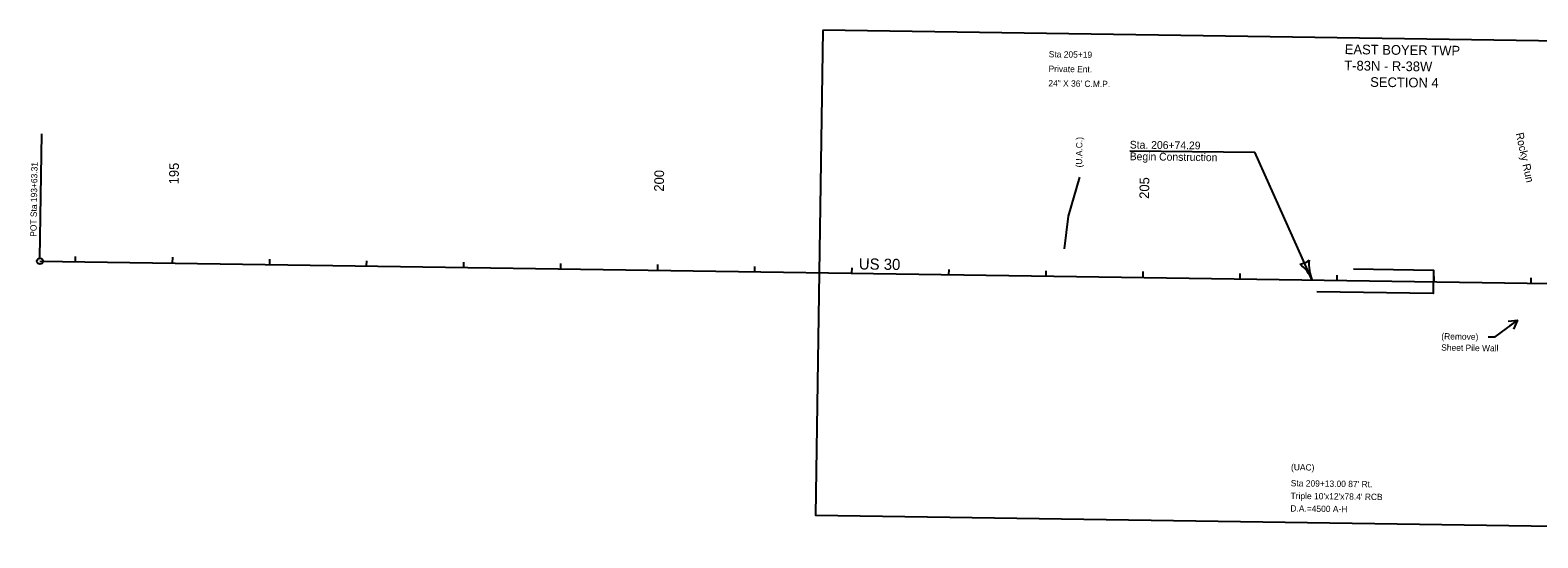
# Model space of a CAD drawing. Extents: x 14295116 to 14303545, y 8637313 to 8653417.
# Drawn here: x 14299276 to 14300829, y 8652720 to 8653243 of the extents above; entities that cross this region are included whole.
import ezdxf

# ---------------------------------------------------------------- set-up
doc = ezdxf.new("R2010")
doc.units = 0
for name, color, linetype in [('dsnCellElements', 7, 'Continuous'), ('dsnCellsNorthArrow', 7, 'Continuous'), ('dsnNonPlotable', 7, 'Continuous'), ('dsnProfileBarGraphArrows', 7, 'Continuous'), ('dsnProfileGradePropCircle', 7, 'Continuous'), ('dsnShtPortLev01', 7, 'Continuous'), ('dsnTextCulvertProp', 7, 'Continuous'), ('dsnTextEntranceProp', 7, 'Continuous'), ('dsnTextNote', 7, 'Continuous'), ('dsnTextProfileBarGraphLeft', 7, 'Continuous'), ('dsnTextProfileBarGraphRight', 7, 'Continuous'), ('dsnTextProfileGradeProp', 7, 'Continuous'), ('dsnTextRoadwayLabel', 7, 'Continuous'), ('PhoNotesDesign', 7, 'Continuous')]:
    doc.layers.add(name, color=color, linetype=linetype)

msp = doc.modelspace()

# ---------------------------------------------------------------- linework, layer by layer
at = {"layer": 'dsnCellElements'}
msp.add_lwpolyline([(14300092.5, 8653243.2), (14300085, 8652743.2), (14301652.4, 8652720), (14301659.8, 8653219.9)], close=True, dxfattribs=at)
at = {"layer": 'dsnCellsNorthArrow'}
for p in [(14300408.9, 8653118.9), (14300596.8, 8652985.7)]:
    msp.add_line(p, (14300537.8, 8653117.3), dxfattribs=at)
for centre, radius, start, end in [((14300582.8, 8653018.5), 16.4, 275.2724, 310.7391), ((14300557.6, 8652969.1), 42.5, 23.0058, 51.0783), ((14300635.9, 8653002.3), 42.5, 174.9333, 203.0058)]:
    msp.add_arc(centre, radius, start, end, dxfattribs=at)
at = {"layer": 'dsnProfileBarGraphArrows'}
for p in [(14300798.7, 8652943.3), (14300800.6, 8652938.4), (14300804.6, 8652935.2)]:
    msp.add_line(p, (14300808.6, 8652944.4), dxfattribs=at)
msp.add_lwpolyline([(14300778, 8652927), (14300785.4, 8652927.2), (14300808.6, 8652944.4)], dxfattribs=at)
at = {"layer": 'dsnProfileGradePropCircle'}
msp.add_line((14299285.9, 8653008.3), (14299287.8, 8653136.2), dxfattribs=at)
msp.add_circle((14299285.9, 8653005.1), 3.13, dxfattribs=at)
at = {"layer": 'dsnShtPortLev01'}
msp.add_line((14299285.9, 8653005.1), (14302066.2, 8652963.9), dxfattribs=at)
at = {"layer": 'dsnTextCulvertProp'}
msp.add_lwpolyline([(14300639.5, 8652997.1), (14300721.7, 8652995.8), (14300721.3, 8652971.8), (14300601.6, 8652973.6)], dxfattribs=at)
at = {"layer": 'dsnTextEntranceProp'}
msp.add_lwpolyline([(14300341.5, 8653017.9), (14300345.8, 8653051.5), (14300357.4, 8653091.8)], dxfattribs=at)
at = {"layer": 'dsnTextProfileGradeProp'}
for p, q in [((14299322.6, 8653004.6), (14299322.6, 8653010.1)), ((14299422.6, 8653003.1), (14299422.7, 8653009.2)), ((14299522.6, 8653001.6), (14299522.6, 8653007.1)), ((14299622.5, 8653000.2), (14299622.6, 8653005.6)), ((14299722.5, 8652998.7), (14299722.6, 8653004.2)), ((14299822.5, 8652997.2), (14299822.6, 8653002.7)), ((14299922.5, 8652995.7), (14299922.6, 8653001.8)), ((14300022.5, 8652994.2), (14300022.6, 8652999.7)), ((14300122.5, 8652992.7), (14300122.6, 8652998.2)), ((14300222.5, 8652991.2), (14300222.6, 8652996.7)), ((14300322.5, 8652989.8), (14300322.6, 8652995.3)), ((14300422.5, 8652988.3), (14300422.6, 8652994.4)), ((14300522.5, 8652986.8), (14300522.6, 8652992.3)), ((14300622.5, 8652985.3), (14300622.5, 8652990.8)), ((14300722.5, 8652983.8), (14300722.5, 8652989.3)), ((14300822.4, 8652982.3), (14300822.5, 8652987.8))]:
    msp.add_line(p, q, dxfattribs=at)
at = {"layer": 'PhoNotesDesign'}
msp.add_line((14299285.9, 8653005.1), (14303544.9, 8652941.9), dxfattribs=at)

# ---------------------------------------------------------------- texts
at = {"layer": 'dsnCellsNorthArrow'}
for s, p in [('Sta. 206+74.29', (14300408.8, 8653121.2)), ('Begin Construction', (14300408.7, 8653109.2))]:
    msp.add_text(s, height=8, rotation=359.2807, dxfattribs=at).set_placement(p)
at = {"layer": 'dsnNonPlotable'}
for s, p in [('195', (14299428.8, 8653084.2)), ('200', (14299928.7, 8653076.7)), ('205', (14300428.7, 8653069.3))]:
    msp.add_text(s, height=10, rotation=89.1493, dxfattribs=at).set_placement(p)
at = {"layer": 'dsnProfileBarGraphArrows'}
for s, height, rotation, p in [('(U.A.C.)', 6.5, 89.2807, (14300359.7, 8653101.7)), ('US 30', 11.5, 359.1493, (14300129.6, 8652996.6)), ('(Remove)', 6.5, 359.2287, (14300729.8, 8652924.5)), ('Sheet Pile Wall', 6.5, 359.2287, (14300729.7, 8652912.9))]:
    msp.add_text(s, height=height, rotation=rotation, dxfattribs=at).set_placement(p)
at = {"layer": 'dsnProfileGradePropCircle'}
msp.add_text('POT Sta 193+63.31', height=6.5, rotation=89.1493, dxfattribs=at).set_placement((14299282.3, 8653030.2))
at = {"layer": 'dsnTextNote'}
msp.add_text('Rocky Run', height=8, rotation=282.2565, dxfattribs=at).set_placement((14300806.5, 8653136.7))
at = {"layer": 'dsnTextProfileBarGraphLeft'}
for s, p in [('Sta 205+19', (14300325.3, 8653215.2)), ('Private Ent.', (14300325.1, 8653200.2)), ('24" X 36\' C.M.P.', (14300324.9, 8653185.3)), ("Sta 209+13.00 87' Rt.", (14300574.7, 8652773.1)), ("Triple 10'x12'x78.4' RCB", (14300574.5, 8652760.1)), ('D.A.=4500 A-H', (14300574.3, 8652747.1))]:
    msp.add_text(s, height=6.5, rotation=359.2287, dxfattribs=at).set_placement(p)
at = {"layer": 'dsnTextProfileBarGraphRight'}
msp.add_text('(UAC)', height=6.5, rotation=359.2287, dxfattribs=at).set_placement((14300574.9, 8652789.6))
at = {"layer": 'dsnTextRoadwayLabel'}
for s, p in [('EAST BOYER TWP', (14300630.3, 8653218.5)), ('T-83N - R-38W', (14300629.8, 8653201.8)), ('SECTION 4', (14300656.5, 8653184.8))]:
    msp.add_text(s, height=10, rotation=359.2807, dxfattribs=at).set_placement(p)

doc.saveas('drawing.dxf')
